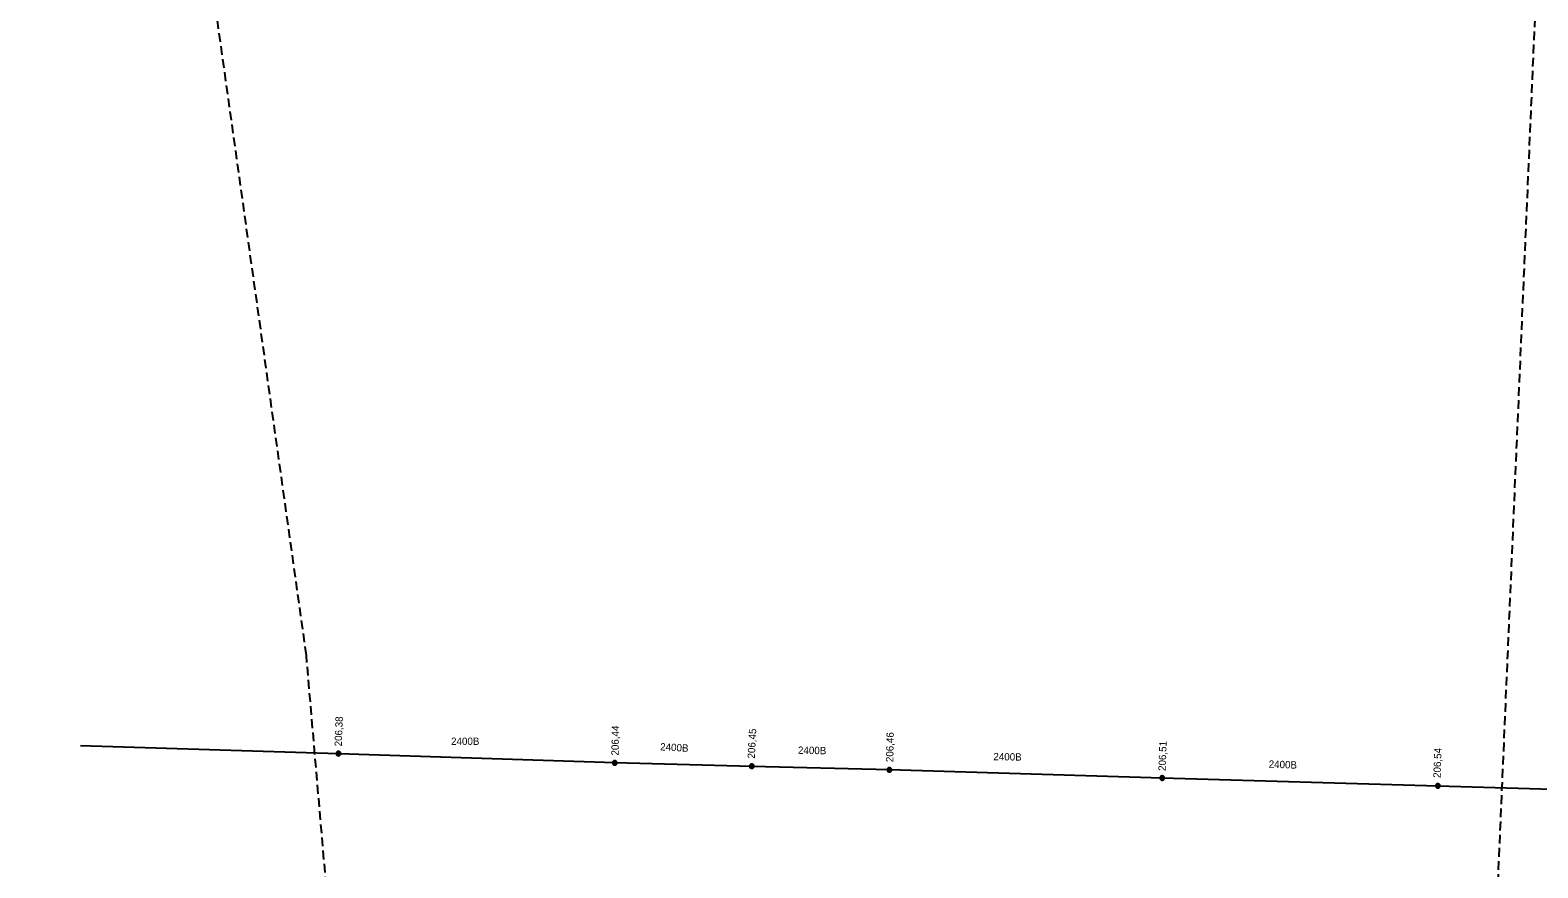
# Model space of a CAD drawing. Extents: x -740786 to -740000, y -1046854 to -1046100.
# Drawn here: x -740626.7 to -740462.1, y -1046741 to -1046649.5 of the extents above; entities that cross this region are included whole.
import ezdxf

# ---------------------------------------------------------------- set-up
doc = ezdxf.new("R2010")
doc.units = 0
doc.header["$LTSCALE"] = 0.32
doc.linetypes.add('LONG_DASHED', pattern=[7.5, 6, -1.5])
doc.linetypes.add('MEDIUM_DASHED', pattern=[4.5, 3, -1.5])
doc.layers.add('1', color=7, linetype='Continuous')
for name, color, linetype, lineweight in [('18', 7, 'Continuous', 13), ('20', 7, 'LONG_DASHED', 25), ('63', 7, 'MEDIUM_DASHED', 25)]:
    doc.layers.add(name, color=color, linetype=linetype, lineweight=lineweight)

msp = doc.modelspace()

# ---------------------------------------------------------------- linework, layer by layer
at = {"layer": '18'}
for points in [[(-740592.766, -1046728.497), (-740592.772, -1046728.441), (-740592.789, -1046728.388), (-740592.818, -1046728.339), (-740592.856, -1046728.298), (-740592.902, -1046728.266), (-740592.954, -1046728.244), (-740593.009, -1046728.233), (-740593.065, -1046728.235), (-740593.12, -1046728.248), (-740593.171, -1046728.273), (-740593.215, -1046728.308), (-740593.251, -1046728.351), (-740593.276, -1046728.401), (-740593.291, -1046728.456), (-740593.294, -1046728.512), (-740593.285, -1046728.567), (-740593.264, -1046728.62), (-740593.233, -1046728.666), (-740593.193, -1046728.705), (-740593.145, -1046728.735), (-740593.092, -1046728.754), (-740593.036, -1046728.761), (-740592.98, -1046728.757), (-740592.926, -1046728.74), (-740592.877, -1046728.713), (-740592.835, -1046728.675), (-740592.802, -1046728.63), (-740592.779, -1046728.579), (-740592.767, -1046728.524)], [(-740592.825, -1046728.5), (-740592.831, -1046728.451), (-740592.849, -1046728.405), (-740592.877, -1046728.364), (-740592.914, -1046728.331), (-740592.958, -1046728.309), (-740593.006, -1046728.297), (-740593.055, -1046728.297), (-740593.103, -1046728.309), (-740593.147, -1046728.332), (-740593.184, -1046728.365), (-740593.212, -1046728.406), (-740593.229, -1046728.453), (-740593.235, -1046728.502), (-740593.228, -1046728.551), (-740593.21, -1046728.597), (-740593.182, -1046728.637), (-740593.145, -1046728.67), (-740593.101, -1046728.692), (-740593.052, -1046728.704), (-740593.003, -1046728.703), (-740592.955, -1046728.691), (-740592.912, -1046728.667), (-740592.875, -1046728.634), (-740592.847, -1046728.593), (-740592.831, -1046728.546)], [(-740592.884, -1046728.504), (-740592.89, -1046728.462), (-740592.907, -1046728.424), (-740592.935, -1046728.393), (-740592.97, -1046728.37), (-740593.01, -1046728.359), (-740593.052, -1046728.359), (-740593.092, -1046728.371), (-740593.127, -1046728.394), (-740593.154, -1046728.426), (-740593.171, -1046728.464), (-740593.176, -1046728.505), (-740593.17, -1046728.547), (-740593.152, -1046728.584), (-740593.124, -1046728.616), (-740593.088, -1046728.638), (-740593.048, -1046728.649), (-740593.006, -1046728.648), (-740592.966, -1046728.635), (-740592.932, -1046728.612), (-740592.905, -1046728.579), (-740592.889, -1046728.541)], [(-740562.595, -1046729.507), (-740562.601, -1046729.451), (-740562.618, -1046729.398), (-740562.647, -1046729.349), (-740562.685, -1046729.308), (-740562.731, -1046729.276), (-740562.783, -1046729.254), (-740562.838, -1046729.243), (-740562.894, -1046729.245), (-740562.949, -1046729.258), (-740563, -1046729.283), (-740563.044, -1046729.318), (-740563.08, -1046729.361), (-740563.105, -1046729.411), (-740563.12, -1046729.466), (-740563.123, -1046729.522), (-740563.114, -1046729.577), (-740563.093, -1046729.63), (-740563.062, -1046729.676), (-740563.022, -1046729.715), (-740562.974, -1046729.745), (-740562.921, -1046729.764), (-740562.865, -1046729.771), (-740562.809, -1046729.767), (-740562.755, -1046729.75), (-740562.706, -1046729.723), (-740562.664, -1046729.685), (-740562.631, -1046729.64), (-740562.608, -1046729.589), (-740562.596, -1046729.534)], [(-740562.654, -1046729.51), (-740562.66, -1046729.461), (-740562.678, -1046729.415), (-740562.706, -1046729.374), (-740562.743, -1046729.341), (-740562.787, -1046729.319), (-740562.835, -1046729.307), (-740562.884, -1046729.307), (-740562.932, -1046729.319), (-740562.976, -1046729.342), (-740563.013, -1046729.375), (-740563.041, -1046729.416), (-740563.058, -1046729.463), (-740563.064, -1046729.512), (-740563.057, -1046729.561), (-740563.039, -1046729.607), (-740563.011, -1046729.647), (-740562.974, -1046729.68), (-740562.93, -1046729.702), (-740562.881, -1046729.714), (-740562.832, -1046729.713), (-740562.784, -1046729.701), (-740562.741, -1046729.677), (-740562.704, -1046729.644), (-740562.676, -1046729.603), (-740562.66, -1046729.556)], [(-740562.713, -1046729.514), (-740562.719, -1046729.472), (-740562.736, -1046729.434), (-740562.764, -1046729.403), (-740562.799, -1046729.38), (-740562.839, -1046729.369), (-740562.881, -1046729.369), (-740562.921, -1046729.381), (-740562.956, -1046729.404), (-740562.983, -1046729.436), (-740563, -1046729.474), (-740563.005, -1046729.515), (-740562.999, -1046729.557), (-740562.981, -1046729.594), (-740562.953, -1046729.626), (-740562.917, -1046729.648), (-740562.877, -1046729.659), (-740562.835, -1046729.658), (-740562.795, -1046729.645), (-740562.761, -1046729.622), (-740562.734, -1046729.589), (-740562.718, -1046729.551)], [(-740547.635, -1046729.877), (-740547.641, -1046729.821), (-740547.657, -1046729.768), (-740547.686, -1046729.719), (-740547.725, -1046729.678), (-740547.771, -1046729.646), (-740547.823, -1046729.624), (-740547.878, -1046729.613), (-740547.934, -1046729.615), (-740547.989, -1046729.628), (-740548.039, -1046729.653), (-740548.084, -1046729.688), (-740548.12, -1046729.731), (-740548.145, -1046729.781), (-740548.16, -1046729.836), (-740548.163, -1046729.892), (-740548.154, -1046729.947), (-740548.133, -1046730), (-740548.102, -1046730.046), (-740548.061, -1046730.085), (-740548.014, -1046730.115), (-740547.961, -1046730.134), (-740547.905, -1046730.141), (-740547.848, -1046730.137), (-740547.794, -1046730.12), (-740547.745, -1046730.093), (-740547.704, -1046730.055), (-740547.671, -1046730.01), (-740547.647, -1046729.959), (-740547.636, -1046729.904)], [(-740547.694, -1046729.88), (-740547.7, -1046729.831), (-740547.718, -1046729.785), (-740547.745, -1046729.744), (-740547.782, -1046729.711), (-740547.826, -1046729.689), (-740547.875, -1046729.677), (-740547.924, -1046729.677), (-740547.972, -1046729.689), (-740548.016, -1046729.712), (-740548.053, -1046729.745), (-740548.081, -1046729.786), (-740548.098, -1046729.833), (-740548.103, -1046729.882), (-740548.097, -1046729.931), (-740548.079, -1046729.977), (-740548.051, -1046730.017), (-740548.014, -1046730.05), (-740547.97, -1046730.072), (-740547.921, -1046730.084), (-740547.872, -1046730.083), (-740547.824, -1046730.071), (-740547.781, -1046730.047), (-740547.744, -1046730.014), (-740547.716, -1046729.973), (-740547.7, -1046729.926)], [(-740547.753, -1046729.884), (-740547.759, -1046729.842), (-740547.776, -1046729.804), (-740547.804, -1046729.773), (-740547.838, -1046729.75), (-740547.879, -1046729.739), (-740547.921, -1046729.739), (-740547.961, -1046729.751), (-740547.995, -1046729.774), (-740548.022, -1046729.806), (-740548.039, -1046729.844), (-740548.044, -1046729.885), (-740548.039, -1046729.927), (-740548.021, -1046729.964), (-740547.993, -1046729.996), (-740547.956, -1046730.018), (-740547.917, -1046730.029), (-740547.875, -1046730.028), (-740547.835, -1046730.015), (-740547.801, -1046729.992), (-740547.774, -1046729.959), (-740547.758, -1046729.921)], [(-740532.615, -1046730.267), (-740532.62, -1046730.211), (-740532.637, -1046730.158), (-740532.666, -1046730.109), (-740532.705, -1046730.068), (-740532.75, -1046730.036), (-740532.803, -1046730.014), (-740532.858, -1046730.003), (-740532.914, -1046730.005), (-740532.968, -1046730.018), (-740533.019, -1046730.043), (-740533.064, -1046730.078), (-740533.1, -1046730.121), (-740533.125, -1046730.171), (-740533.14, -1046730.226), (-740533.142, -1046730.282), (-740533.134, -1046730.337), (-740533.113, -1046730.39), (-740533.081, -1046730.436), (-740533.041, -1046730.475), (-740532.994, -1046730.505), (-740532.941, -1046730.524), (-740532.885, -1046730.531), (-740532.828, -1046730.527), (-740532.774, -1046730.51), (-740532.725, -1046730.483), (-740532.684, -1046730.445), (-740532.651, -1046730.4), (-740532.627, -1046730.349), (-740532.615, -1046730.294)], [(-740532.674, -1046730.27), (-740532.679, -1046730.221), (-740532.698, -1046730.175), (-740532.725, -1046730.134), (-740532.762, -1046730.101), (-740532.806, -1046730.079), (-740532.855, -1046730.067), (-740532.904, -1046730.067), (-740532.951, -1046730.079), (-740532.995, -1046730.102), (-740533.032, -1046730.135), (-740533.061, -1046730.176), (-740533.078, -1046730.223), (-740533.083, -1046730.272), (-740533.076, -1046730.321), (-740533.059, -1046730.367), (-740533.031, -1046730.407), (-740532.994, -1046730.44), (-740532.95, -1046730.462), (-740532.901, -1046730.474), (-740532.852, -1046730.473), (-740532.804, -1046730.461), (-740532.761, -1046730.437), (-740532.723, -1046730.404), (-740532.696, -1046730.363), (-740532.679, -1046730.316)], [(-740532.733, -1046730.274), (-740532.739, -1046730.232), (-740532.755, -1046730.194), (-740532.784, -1046730.163), (-740532.818, -1046730.14), (-740532.858, -1046730.129), (-740532.901, -1046730.129), (-740532.941, -1046730.141), (-740532.975, -1046730.164), (-740533.002, -1046730.196), (-740533.019, -1046730.234), (-740533.024, -1046730.275), (-740533.019, -1046730.317), (-740533, -1046730.354), (-740532.973, -1046730.386), (-740532.936, -1046730.408), (-740532.897, -1046730.419), (-740532.855, -1046730.418), (-740532.815, -1046730.405), (-740532.781, -1046730.382), (-740532.754, -1046730.349), (-740532.738, -1046730.311)], [(-740502.826, -1046731.167), (-740502.831, -1046731.111), (-740502.848, -1046731.058), (-740502.877, -1046731.009), (-740502.916, -1046730.968), (-740502.962, -1046730.936), (-740503.014, -1046730.914), (-740503.069, -1046730.903), (-740503.125, -1046730.905), (-740503.179, -1046730.918), (-740503.23, -1046730.943), (-740503.275, -1046730.978), (-740503.311, -1046731.021), (-740503.336, -1046731.071), (-740503.351, -1046731.126), (-740503.353, -1046731.182), (-740503.345, -1046731.237), (-740503.324, -1046731.29), (-740503.293, -1046731.336), (-740503.252, -1046731.375), (-740503.205, -1046731.405), (-740503.152, -1046731.424), (-740503.096, -1046731.431), (-740503.039, -1046731.427), (-740502.985, -1046731.41), (-740502.936, -1046731.383), (-740502.895, -1046731.345), (-740502.862, -1046731.3), (-740502.838, -1046731.249), (-740502.826, -1046731.194)], [(-740502.885, -1046731.17), (-740502.891, -1046731.121), (-740502.909, -1046731.075), (-740502.936, -1046731.034), (-740502.973, -1046731.001), (-740503.017, -1046730.979), (-740503.066, -1046730.967), (-740503.115, -1046730.967), (-740503.163, -1046730.979), (-740503.206, -1046731.002), (-740503.244, -1046731.035), (-740503.272, -1046731.076), (-740503.289, -1046731.123), (-740503.294, -1046731.172), (-740503.288, -1046731.221), (-740503.27, -1046731.267), (-740503.242, -1046731.307), (-740503.205, -1046731.34), (-740503.161, -1046731.362), (-740503.112, -1046731.374), (-740503.063, -1046731.373), (-740503.015, -1046731.361), (-740502.972, -1046731.337), (-740502.934, -1046731.304), (-740502.907, -1046731.263), (-740502.891, -1046731.216)], [(-740502.944, -1046731.174), (-740502.95, -1046731.132), (-740502.967, -1046731.094), (-740502.995, -1046731.063), (-740503.029, -1046731.04), (-740503.07, -1046731.029), (-740503.112, -1046731.029), (-740503.152, -1046731.041), (-740503.186, -1046731.064), (-740503.213, -1046731.096), (-740503.23, -1046731.134), (-740503.235, -1046731.175), (-740503.23, -1046731.217), (-740503.212, -1046731.254), (-740503.184, -1046731.286), (-740503.147, -1046731.308), (-740503.108, -1046731.319), (-740503.066, -1046731.318), (-740503.026, -1046731.305), (-740502.992, -1046731.282), (-740502.965, -1046731.249), (-740502.949, -1046731.211)], [(-740472.725, -1046732.027), (-740472.73, -1046731.971), (-740472.747, -1046731.918), (-740472.776, -1046731.869), (-740472.815, -1046731.828), (-740472.86, -1046731.796), (-740472.913, -1046731.774), (-740472.968, -1046731.763), (-740473.024, -1046731.765), (-740473.078, -1046731.778), (-740473.129, -1046731.803), (-740473.174, -1046731.838), (-740473.21, -1046731.881), (-740473.235, -1046731.931), (-740473.25, -1046731.986), (-740473.252, -1046732.042), (-740473.244, -1046732.097), (-740473.223, -1046732.15), (-740473.191, -1046732.196), (-740473.151, -1046732.235), (-740473.103, -1046732.265), (-740473.051, -1046732.284), (-740472.995, -1046732.291), (-740472.938, -1046732.287), (-740472.884, -1046732.27), (-740472.835, -1046732.243), (-740472.794, -1046732.205), (-740472.761, -1046732.16), (-740472.737, -1046732.109), (-740472.725, -1046732.054)], [(-740472.784, -1046732.03), (-740472.789, -1046731.981), (-740472.808, -1046731.935), (-740472.835, -1046731.894), (-740472.872, -1046731.861), (-740472.916, -1046731.839), (-740472.965, -1046731.827), (-740473.014, -1046731.827), (-740473.061, -1046731.839), (-740473.105, -1046731.862), (-740473.142, -1046731.895), (-740473.171, -1046731.936), (-740473.188, -1046731.983), (-740473.193, -1046732.032), (-740473.186, -1046732.081), (-740473.169, -1046732.127), (-740473.141, -1046732.167), (-740473.103, -1046732.2), (-740473.059, -1046732.222), (-740473.011, -1046732.234), (-740472.962, -1046732.233), (-740472.914, -1046732.221), (-740472.87, -1046732.197), (-740472.833, -1046732.164), (-740472.806, -1046732.123), (-740472.789, -1046732.076)], [(-740472.843, -1046732.034), (-740472.848, -1046731.992), (-740472.865, -1046731.954), (-740472.894, -1046731.923), (-740472.928, -1046731.9), (-740472.968, -1046731.889), (-740473.011, -1046731.889), (-740473.051, -1046731.901), (-740473.085, -1046731.924), (-740473.112, -1046731.956), (-740473.129, -1046731.994), (-740473.134, -1046732.035), (-740473.129, -1046732.077), (-740473.11, -1046732.114), (-740473.083, -1046732.146), (-740473.046, -1046732.168), (-740473.007, -1046732.179), (-740472.965, -1046732.178), (-740472.924, -1046732.165), (-740472.891, -1046732.142), (-740472.864, -1046732.109), (-740472.848, -1046732.071)]]:
    msp.add_lwpolyline(points, close=True, dxfattribs=at)
at = {"layer": '20', "linetype": 'Continuous'}
for points in [[(-740562.859, -1046729.52), (-740593.03, -1046728.51), (-740621.18, -1046727.63)], [(-740562.859, -1046729.52), (-740593.03, -1046728.51), (-740621.18, -1046727.63)], [(-740442.98, -1046732.94), (-740472.989, -1046732.04), (-740503.09, -1046731.18), (-740532.879, -1046730.28), (-740547.899, -1046729.89), (-740562.859, -1046729.52)], [(-740442.98, -1046732.94), (-740472.989, -1046732.04), (-740503.09, -1046731.18), (-740532.879, -1046730.28), (-740547.899, -1046729.89), (-740562.859, -1046729.52)]]:
    msp.add_lwpolyline(points, dxfattribs=at)
at = {"layer": '63'}
msp.add_lwpolyline([(-740455.336, -1046482.714), (-740468.522, -1046790.977), (-740468.522, -1046790.979), (-740468.523, -1046790.981), (-740468.524, -1046790.982), (-740468.525, -1046790.984), (-740468.527, -1046790.985), (-740468.529, -1046790.986), (-740468.531, -1046790.986), (-740589.04, -1046804.624), (-740589.042, -1046804.624), (-740589.044, -1046804.624), (-740589.046, -1046804.623), (-740589.047, -1046804.622), (-740589.049, -1046804.621), (-740589.05, -1046804.619), (-740589.05, -1046804.617), (-740589.051, -1046804.615), (-740596.533, -1046717.763), (-740626.694, -1046502.274)], dxfattribs=at)

# ---------------------------------------------------------------- texts
at = {"layer": '1'}
for s, rotation, p in [('206,38', 88, (-740592.666, -1046727.718)), ('206,44', 89, (-740562.444, -1046728.713)), ('206,45', 87, (-740547.574, -1046729.055)), ('206,46', 89, (-740532.448, -1046729.434)), ('2400B ', 357, (-740557.922, -1046728.141)), ('2400B ', 359, (-740542.863, -1046728.518)), ('206,51', 88, (-740502.713, -1046730.403)), ('206,54', 88, (-740472.692, -1046731.167)), ('2400B ', 359, (-740521.528, -1046729.216)), ('2400B ', 358, (-740491.474, -1046730.035))]:
    msp.add_text(s, height=0.8, rotation=rotation, dxfattribs=at).set_placement(p)
msp.add_text('2400B ', height=0.8, dxfattribs=at).set_placement((-740580.735, -1046727.548))

doc.saveas('drawing.dxf')
